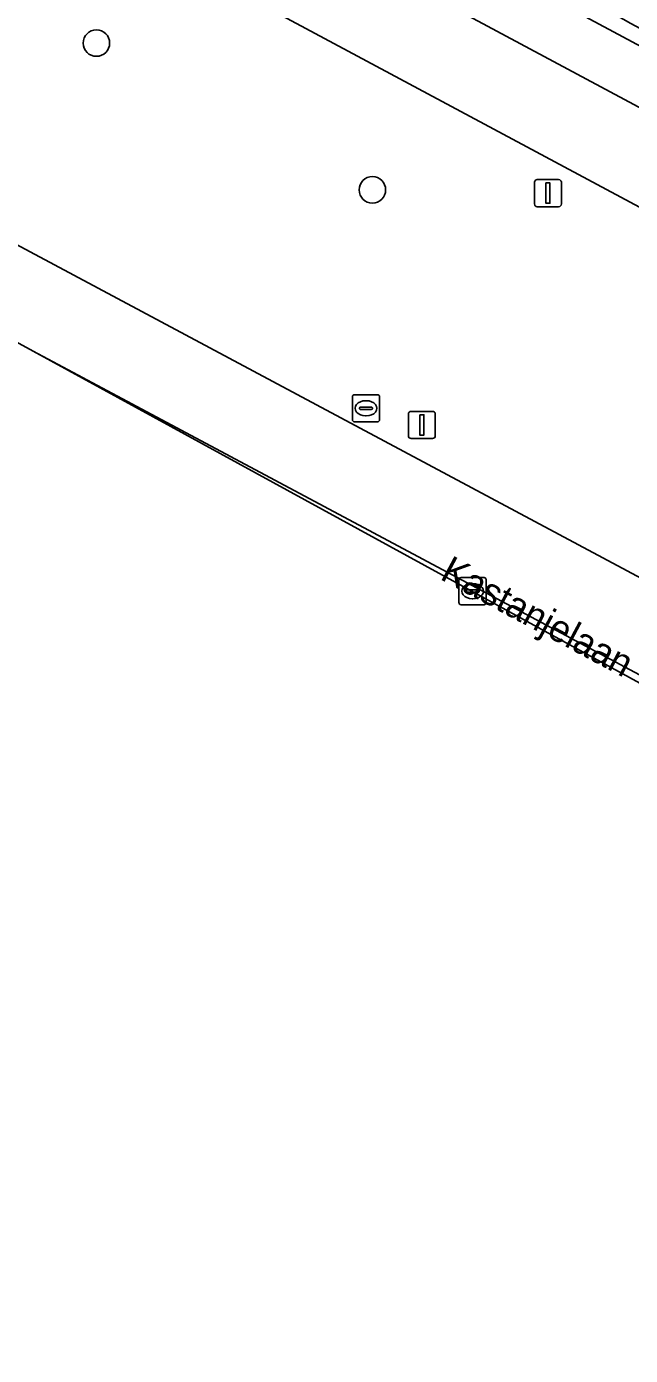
# Model space of a CAD drawing. Extents: x 159489 to 160304, y 383825 to 384531.
# Drawn here: x 160020.81 to 160043.09, y 383830.94 to 383879.92 of the extents above; entities that cross this region are included whole.
import ezdxf

# ---------------------------------------------------------------- set-up
doc = ezdxf.new("R2010")
doc.units = 0
for name, color, linetype in [('IMGEO_Berm_groen', 7, 'Continuous'), ('IMGEO_Boom', 7, 'Continuous'), ('IMGEO_Kolk', 7, 'Continuous'), ('IMGEO_Lichtmast', 7, 'Continuous'), ('IMGEO_Openbare_ruimte_label', 7, 'Continuous'), ('IMGEO_Parkeervlak_open', 7, 'Continuous'), ('IMGEO_Rijbaan_lokaal_gesloten', 7, 'Continuous'), ('IMGEO_Rijbaan_lokaal_open', 7, 'Continuous'), ('IMGEO_Rioolput', 7, 'Continuous')]:
    doc.layers.add(name, color=color, linetype=linetype)

msp = doc.modelspace()

# ---------------------------------------------------------------- linework, layer by layer
at = {"layer": 'IMGEO_Berm_groen'}
for points in [[(160061.966, 383862.581), (160058.689, 383864.804), (160056.095, 383866.396), (160053.478, 383867.874), (159970.742, 383912.143)], [(159969.898, 383898.866), (160055.851, 383852.975)]]:
    msp.add_lwpolyline(points, dxfattribs=at)
at = {"layer": 'IMGEO_Boom'}
for centre in [(160023.383, 383879.308), (160033.566, 383873.897)]:
    msp.add_circle(centre, 0.489, dxfattribs=at)
at = {"layer": 'IMGEO_Kolk'}
for p, q in [((160036.837, 383859.609), (160037.689, 383859.609)), ((160036.762, 383858.683), (160036.762, 383859.535)), ((160037.064, 383859.152), (160037.462, 383859.152)), ((160037.25, 383859.389), (160037.275, 383859.389)), ((160037.763, 383859.535), (160037.763, 383858.683)), ((160037.021, 383859.103), (160037.021, 383859.115)), ((160037.459, 383859.066), (160037.061, 383859.066)), ((160037.273, 383858.829), (160037.248, 383858.829)), ((160037.505, 383859.115), (160037.505, 383859.103)), ((160037.689, 383858.609), (160036.837, 383858.609))]:
    msp.add_line(p, q, dxfattribs=at)
for points in [[(160036.837, 383859.609), (160037.689, 383859.609)], [(160036.762, 383858.683), (160036.762, 383859.535)], [(160037.763, 383859.535), (160037.763, 383858.683)], [(160037.689, 383858.609), (160036.837, 383858.609)]]:
    msp.add_lwpolyline(points, dxfattribs=at)
for centre, radius, start, end in [((160036.839, 383859.533), 0.0765, 91.552, 178.448), ((160036.839, 383859.533), 0.0765, 91.552, 178.448), ((160037.687, 383859.533), 0.0765, 1.552, 88.448), ((160037.687, 383859.533), 0.0765, 1.552, 88.448), ((160037.061, 383859.112), 0.0403, 85.8775, 175.7526), ((160037.466, 383859.114), 0.0386, 1.7309, 96.639), ((160036.839, 383858.685), 0.0765, 181.552, 268.448), ((160036.839, 383858.685), 0.0765, 181.552, 268.448), ((160037.058, 383859.102), 0.0366, 178.938, 274.7102), ((160037.462, 383859.109), 0.043, 264.8664, 352.4533), ((160037.687, 383858.685), 0.0765, 271.552, 358.448), ((160037.687, 383858.685), 0.0765, 271.552, 358.448)]:
    msp.add_arc(centre, radius, start, end, dxfattribs=at)
for centre, major_axis, ratio, start_param, end_param in [((160037.249, 383859.109), (-0.387, 0.002), 0.722429, 4.712389, 7.853982), ((160037.274, 383859.109), (-0.39, 0.002), 0.717154, 1.570796, 4.712389)]:
    msp.add_ellipse(centre, major_axis=major_axis, ratio=ratio, start_param=start_param, end_param=end_param, dxfattribs=at)
at = {"layer": 'IMGEO_Lichtmast'}
for p, q in [((160039.549, 383873.378), (160039.549, 383874.178)), ((160039.549, 383874.178), (160039.549, 383873.378)), ((160039.649, 383874.278), (160040.439, 383874.278)), ((160040.439, 383874.278), (160039.649, 383874.278)), ((160040.539, 383874.178), (160040.539, 383873.378)), ((160040.539, 383873.378), (160040.539, 383874.178)), ((160040.439, 383873.278), (160039.649, 383873.278)), ((160039.649, 383873.278), (160040.439, 383873.278)), ((160034.896, 383864.835), (160034.896, 383865.635)), ((160034.896, 383865.635), (160034.896, 383864.835)), ((160034.996, 383865.735), (160035.786, 383865.735)), ((160035.786, 383865.735), (160034.996, 383865.735)), ((160035.886, 383865.635), (160035.886, 383864.835)), ((160035.886, 383864.835), (160035.886, 383865.635)), ((160035.786, 383864.735), (160034.996, 383864.735)), ((160034.996, 383864.735), (160035.786, 383864.735))]:
    msp.add_line(p, q, dxfattribs=at)
for points in [[(160039.969, 383874.153), (160040.119, 383874.153), (160040.119, 383873.403), (160039.969, 383873.403), (160039.969, 383874.153)], [(160035.316, 383865.61), (160035.466, 383865.61), (160035.466, 383864.86), (160035.316, 383864.86), (160035.316, 383865.61)]]:
    msp.add_lwpolyline(points, dxfattribs=at)
for centre, start, end in [((160039.649, 383874.178), 90, 180), ((160039.649, 383874.178), 90, 180), ((160040.439, 383874.178), 0, 90), ((160040.439, 383874.178), 360, 90), ((160039.649, 383873.378), 180, 270), ((160039.649, 383873.378), 180, 270), ((160040.439, 383873.378), 270, 0), ((160040.439, 383873.378), 270, 0), ((160034.996, 383865.635), 90, 180), ((160034.996, 383865.635), 90, 180), ((160035.786, 383865.635), 0, 90), ((160035.786, 383865.635), 360, 90), ((160034.996, 383864.835), 180, 270), ((160034.996, 383864.835), 180, 270), ((160035.786, 383864.835), 270, 0), ((160035.786, 383864.835), 270, 0)]:
    msp.add_arc(centre, 0.1, start, end, dxfattribs=at)
at = {"layer": 'IMGEO_Parkeervlak_open'}
for points in [[(160077.478, 383859.412), (160077.014, 383860.968), (160076.629, 383861.444), (159976.343, 383915.107), (159975.732, 383915.181), (159973.882, 383914.736)], [(159972.412, 383914.912), (160078.438, 383858.214)], [(160021.053, 383867.95), (160082.626, 383834.294), (160082.888, 383834.377)], [(160084.017, 383834.381), (160021.053, 383867.95)]]:
    msp.add_lwpolyline(points, dxfattribs=at)
at = {"layer": 'IMGEO_Rijbaan_lokaal_gesloten'}
for points in [[(160090.385, 383852.127), (160085.336, 383854.619), (160078.438, 383858.214), (159972.412, 383914.912), (159972.242, 383915.004), (159968.826, 383916.839), (159968.691, 383916.912), (159931.196, 383936.985), (159928.655, 383938.312), (159928.469, 383938.485), (159927.034, 383935.543), (159967.228, 383914.015), (159970.742, 383912.143), (160053.478, 383867.874), (160056.095, 383866.396), (160058.689, 383864.804), (160070.255, 383858.888)], [(159925.789, 383923.235), (159921.548, 383925.488), (159920.241, 383923.056), (159975.895, 383892.634), (160021.053, 383867.95)], [(160089.458, 383835.417), (160067.42, 383846.859), (160067.26, 383846.944), (160055.851, 383852.975), (159969.898, 383898.866), (159965.884, 383901.011), (159934.207, 383917.942)], [(160021.053, 383867.95), (160084.017, 383834.381), (160090.47, 383830.94)]]:
    msp.add_lwpolyline(points, dxfattribs=at)
at = {"layer": 'IMGEO_Rijbaan_lokaal_open'}
msp.add_lwpolyline([(160064.303, 383868.741), (160063.368, 383869.231), (160053.74, 383874.368), (160052.805, 383874.863), (160043.105, 383880.034), (160042.167, 383880.557), (160032.58, 383885.694), (160031.613, 383886.21), (160021.978, 383891.374), (160021.012, 383891.859), (160011.376, 383897.042), (160010.406, 383897.525), (160000.817, 383902.692), (159999.865, 383903.217), (159990.178, 383908.381), (159989.219, 383908.89), (159979.676, 383914.003), (159978.73, 383914.512), (159976.659, 383915.636), (159976.343, 383915.107), (160076.629, 383861.444), (160076.914, 383861.98)], close=True, dxfattribs=at)
at = {"layer": 'IMGEO_Rioolput'}
for p, q in [((160032.83, 383865.422), (160032.83, 383866.274)), ((160032.905, 383866.348), (160033.757, 383866.348)), ((160033.318, 383866.128), (160033.343, 383866.128)), ((160033.831, 383866.274), (160033.831, 383865.422)), ((160033.089, 383865.842), (160033.089, 383865.854)), ((160033.527, 383865.805), (160033.129, 383865.805)), ((160033.132, 383865.891), (160033.53, 383865.891)), ((160033.341, 383865.568), (160033.316, 383865.568)), ((160033.573, 383865.854), (160033.573, 383865.842)), ((160033.757, 383865.348), (160032.905, 383865.348))]:
    msp.add_line(p, q, dxfattribs=at)
for points in [[(160032.83, 383865.422), (160032.83, 383866.274)], [(160032.905, 383866.348), (160033.757, 383866.348)], [(160033.831, 383866.274), (160033.831, 383865.422)], [(160033.757, 383865.348), (160032.905, 383865.348)]]:
    msp.add_lwpolyline(points, dxfattribs=at)
for centre, radius, start, end in [((160032.907, 383866.272), 0.0765, 91.552, 178.448), ((160032.907, 383866.272), 0.0765, 91.552, 178.448), ((160033.755, 383866.272), 0.0765, 1.552, 88.448), ((160033.755, 383866.272), 0.0765, 1.552, 88.448), ((160033.129, 383865.851), 0.0403, 85.8775, 175.7526), ((160033.126, 383865.841), 0.0366, 178.938, 274.7102), ((160033.53, 383865.848), 0.043, 264.8664, 352.4533), ((160033.534, 383865.853), 0.0386, 1.7309, 96.639), ((160032.907, 383865.424), 0.0765, 181.552, 268.448), ((160032.907, 383865.424), 0.0765, 181.552, 268.448), ((160033.755, 383865.424), 0.0765, 271.552, 358.448), ((160033.755, 383865.424), 0.0765, 271.552, 358.448)]:
    msp.add_arc(centre, radius, start, end, dxfattribs=at)
for centre, major_axis, ratio, start_param, end_param in [((160033.317, 383865.848), (-0.387, 0.002), 0.722429, 4.712389, 7.853982), ((160033.342, 383865.848), (-0.39, 0.002), 0.717154, 1.570796, 4.712389)]:
    msp.add_ellipse(centre, major_axis=major_axis, ratio=ratio, start_param=start_param, end_param=end_param, dxfattribs=at)

# ---------------------------------------------------------------- texts
at = {"layer": 'IMGEO_Openbare_ruimte_label'}
msp.add_text('Kastanjelaan', height=1, rotation=331.8196, dxfattribs=at).set_placement((160036.023, 383859.566))

doc.saveas('drawing.dxf')
